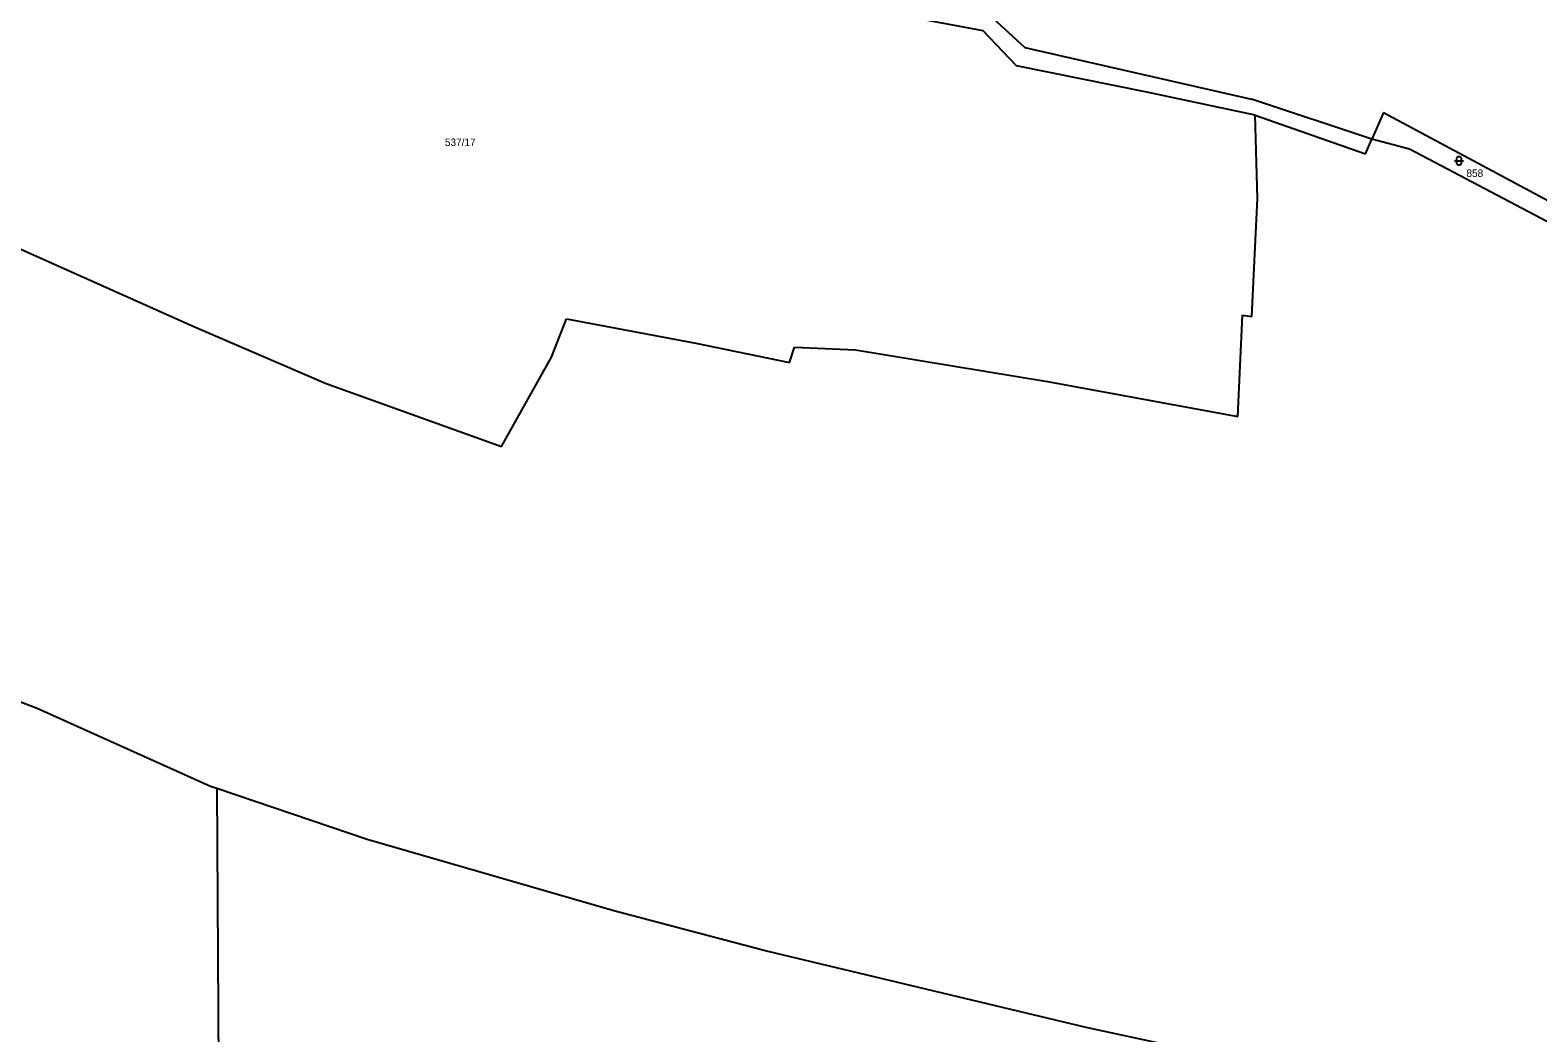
# Model space of a CAD drawing. Extents: x -845995 to -842497, y -1063614 to -1059680.
# Drawn here: x -844318.8 to -843977.7, y -1061856 to -1061629.1 of the extents above; entities that cross this region are included whole.
import ezdxf

# ---------------------------------------------------------------- set-up
doc = ezdxf.new("R2010")
doc.units = 0
for name, color, linetype in [('KN_HRANICE', 7, 'Continuous'), ('KN_KULTURY', 7, 'Continuous'), ('KN_PARCELY', 7, 'Continuous')]:
    doc.layers.add(name, color=color, linetype=linetype)

# ---------------------------------------------------------------- blocks, each defined once
blk = doc.blocks.new('316')
for points in [[(-1, 1), (0.27, 1), (1, 1)], [(-0.5, 1.5), (-0.4, 1.79), (-0.15, 1.97), (0.16, 1.97), (0.41, 1.79), (0.51, 1.5), (0.51, 0.5), (0.41, 0.21), (0.16, 0.03), (-0.15, 0.03), (-0.4, 0.21), (-0.5, 0.5), (-0.5, 1.5)]]:
    blk.add_lwpolyline(points)

msp = doc.modelspace()

# ---------------------------------------------------------------- linework, layer by layer
at = {"layer": 'KN_HRANICE'}
for p, q in [((-844103.23, -1061629.25), (-844138.37, -1061622.75)), ((-844102.06, -1061625.46), (-844093.79, -1061633.07)), ((-844095.68, -1061637.2), (-844103.23, -1061629.25)), ((-844093.79, -1061633.07), (-844042.51, -1061644.71)), ((-844066.15, -1061643.18), (-844095.68, -1061637.2)), ((-844041.68, -1061648.39), (-844066.15, -1061643.18)), ((-844015.31, -1061653.82), (-844042.51, -1061644.71)), ((-844041.16, -1061667.21), (-844041.68, -1061648.39)), ((-844041.68, -1061648.39), (-844016.71, -1061657.07)), ((-844012.66, -1061647.78), (-844015.31, -1061653.82)), ((-844012.66, -1061647.78), (-843964.94, -1061673.27)), ((-844016.71, -1061657.07), (-844015.31, -1061653.82)), ((-844006.77, -1061656.03), (-844015.31, -1061653.82)), ((-843965.97, -1061677.54), (-844006.77, -1061656.03)), ((-844042.46, -1061693.9), (-844041.16, -1061667.21)), ((-844338.96, -1061670.68), (-844281.72, -1061696.14)), ((-844200.84, -1061703.14), (-844197.45, -1061694.42)), ((-844197.45, -1061694.42), (-844168.22, -1061699.91)), ((-844045.58, -1061716.55), (-844044.54, -1061693.64)), ((-844044.54, -1061693.64), (-844042.46, -1061693.9)), ((-844281.72, -1061696.14), (-844251.79, -1061709.03)), ((-844168.22, -1061699.91), (-844147.01, -1061704.34)), ((-844147.01, -1061704.34), (-844145.84, -1061700.82)), ((-844145.84, -1061700.82), (-844132.05, -1061701.47)), ((-844132.05, -1061701.47), (-844088.65, -1061708.61)), ((-844212.16, -1061723.32), (-844200.84, -1061703.14)), ((-844251.79, -1061709.03), (-844212.16, -1061723.32)), ((-844088.65, -1061708.61), (-844045.58, -1061716.55)), ((-844378.49, -1061759.27), (-844317.17, -1061782.48)), ((-844317.17, -1061782.48), (-844277.96, -1061800.13)), ((-844277.96, -1061800.13), (-844276.55, -1061800.61)), ((-844276.55, -1061800.61), (-844242.58, -1061812.17)), ((-844276.55, -1061800.61), (-844275.61, -1061955.01)), ((-844242.58, -1061812.17), (-844186.78, -1061828.31)), ((-844186.78, -1061828.31), (-844151.9, -1061837.48)), ((-844151.9, -1061837.48), (-844079.97, -1061854.68)), ((-844079.97, -1061854.68), (-844048.94, -1061861.4))]:
    msp.add_line(p, q, dxfattribs=at)

# ---------------------------------------------------------------- block references
at = {"layer": 'KN_KULTURY'}
msp.add_blockref('316', (-843995.57, -1061659.68), dxfattribs=at)

# ---------------------------------------------------------------- texts
at = {"layer": 'KN_PARCELY'}
for s, p in [('537/17', (-844224.96, -1061655.34)), ('858', (-843993.88, -1061662.34))]:
    msp.add_text(s, height=1.7, dxfattribs=at).set_placement(p)

doc.saveas('drawing.dxf')
